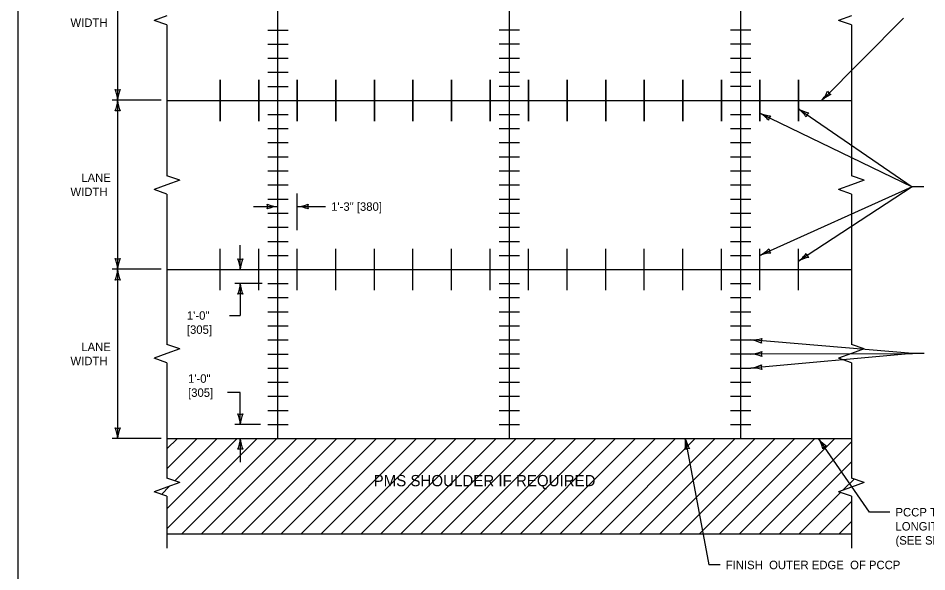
# Model space of a CAD drawing. Extents: x 49979.1 to 50021, y 49966.7 to 50011.4.
# Drawn here: x 49999.38 to 50005.83, y 49992.49 to 49996.41 of the extents above; entities that cross this region are included whole.
import ezdxf

# ---------------------------------------------------------------- set-up
doc = ezdxf.new("R2010")
doc.units = 0
for name, color, linetype in [('Level 1', 7, 'Continuous'), ('Level 2', 7, 'Continuous'), ('Level 3', 7, 'Continuous'), ('Level 4', 7, 'Continuous'), ('Level 6', 7, 'Continuous')]:
    doc.layers.add(name, color=color, linetype=linetype)

msp = doc.modelspace()

# ---------------------------------------------------------------- linework, layer by layer
at = {"layer": 'Level 1'}
for p, q in [((50001.228, 49993.431), (50001.228, 49997.7101)), ((50002.8704, 49993.431), (50002.8704, 49997.7101)), ((50004.5127, 49993.431), (50004.5127, 49997.7101)), ((50000.4398, 49995.8308), (50005.2986, 49995.8308)), ((50000.441, 49994.631), (50005.2998, 49994.631)), ((50000.4398, 49993.431), (50005.2986, 49993.431)), ((50000.4398, 49992.7915), (50001.0793, 49993.431)), ((50000.4398, 49992.9329), (50000.9379, 49993.431)), ((50000.4398, 49993.2157), (50000.6551, 49993.431)), ((50000.4398, 49993.3571), (50000.5136, 49993.431)), ((50000.4962, 49993.1307), (50000.7965, 49993.431)), ((50000.5421, 49992.7524), (50001.2207, 49993.431)), ((50000.6835, 49992.7524), (50001.3622, 49993.431)), ((50000.8249, 49992.7524), (50001.5036, 49993.431)), ((50000.9664, 49992.7524), (50001.645, 49993.431)), ((50001.1078, 49992.7524), (50001.7864, 49993.431)), ((50001.2492, 49992.7524), (50001.9279, 49993.431)), ((50001.3906, 49992.7524), (50002.0693, 49993.431)), ((50001.5321, 49992.7524), (50002.2107, 49993.431)), ((50001.6735, 49992.7524), (50002.3521, 49993.431)), ((50001.8149, 49992.7524), (50002.4935, 49993.431)), ((50001.9563, 49992.7524), (50002.6349, 49993.431)), ((50002.0977, 49992.7524), (50002.7764, 49993.431)), ((50002.2392, 49992.7524), (50002.9178, 49993.431)), ((50002.3806, 49992.7524), (50003.0592, 49993.431)), ((50002.522, 49992.7524), (50003.2007, 49993.431)), ((50002.6634, 49992.7524), (50003.3421, 49993.431)), ((50002.8048, 49992.7524), (50003.4835, 49993.431)), ((50002.9463, 49992.7524), (50003.6249, 49993.431)), ((50003.0877, 49992.7524), (50003.7663, 49993.431)), ((50003.2291, 49992.7524), (50003.9077, 49993.431)), ((50003.3705, 49992.7524), (50004.0492, 49993.431)), ((50003.512, 49992.7524), (50004.1906, 49993.431)), ((50003.6534, 49992.7524), (50004.332, 49993.431)), ((50003.7948, 49992.7524), (50004.4734, 49993.431)), ((50003.9362, 49992.7524), (50004.6149, 49993.431)), ((50004.0776, 49992.7524), (50004.7563, 49993.431)), ((50004.2191, 49992.7524), (50004.8977, 49993.431)), ((50004.3605, 49992.7524), (50005.0391, 49993.431)), ((50004.5019, 49992.7524), (50005.1805, 49993.431)), ((50004.6433, 49992.7524), (50005.2986, 49993.4077)), ((50004.7847, 49992.7524), (50005.2986, 49993.2662)), ((50005.2384, 49993.0646), (50005.3177, 49993.1439)), ((50000.4005, 49993.035), (50000.4578, 49993.0923)), ((50004.9262, 49992.7524), (50005.2221, 49993.0483)), ((50005.0676, 49992.7524), (50005.2986, 49992.9834)), ((50005.209, 49992.7524), (50005.2986, 49992.842)), ((50005.2986, 49992.7524), (50000.4398, 49992.7524))]:
    msp.add_line(p, q, dxfattribs=at)
msp.add_lwpolyline([(49999.3835, 49998.9992), (50016.7501, 49998.9992), (50016.7501, 49987.7988), (49999.3835, 49987.7988)], close=True, dxfattribs=at)
at = {"layer": 'Level 3'}
for p, q in [((50000.0898, 49997.0329), (50000.0898, 49995.8323)), ((50005.6674, 49996.4148), (50005.0876, 49995.8308)), ((50000.3998, 49995.8323), (50000.0498, 49995.8323)), ((50000.0898, 49995.8323), (50000.0898, 49994.6324)), ((50005.8118, 49995.2174), (50005.7276, 49995.2174)), ((50001.365, 49994.9096), (50001.365, 49995.1711)), ((50001.0546, 49995.0775), (50001.228, 49995.0775)), ((50001.365, 49995.0775), (50001.5656, 49995.0775)), ((50000.9605, 49994.6312), (50000.9605, 49994.8046)), ((50000.3998, 49994.6324), (50000.0498, 49994.6324)), ((50000.0898, 49994.6324), (50000.0898, 49993.431)), ((50001.115, 49994.5315), (50000.9205, 49994.5312)), ((50000.9605, 49994.5312), (50000.9605, 49994.3044)), ((50000.8826, 49994.3044), (50000.9605, 49994.3044)), ((50005.816, 49994.0343), (50005.7318, 49994.0343)), ((50000.9605, 49993.7571), (50000.8689, 49993.7571)), ((50000.9605, 49993.5309), (50000.9605, 49993.7571)), ((50001.1038, 49993.5309), (50000.9205, 49993.5309)), ((50000.3998, 49993.431), (50000.0498, 49993.431)), ((50000.9605, 49993.4309), (50000.9605, 49993.2625)), ((50004.1194, 49993.431), (50004.2869, 49992.5341)), ((50005.4272, 49992.9084), (50005.0655, 49993.431)), ((50005.5717, 49992.9084), (50005.4272, 49992.9084)), ((50004.3669, 49992.5341), (50004.2869, 49992.5341))]:
    msp.add_line(p, q, dxfattribs=at)
for points in [[(50004.9233, 49995.7715), (50005.7311, 49995.2174), (50004.9233, 49994.6897)], [(50004.6496, 49995.7402), (50005.7311, 49995.2174), (50004.6496, 49994.7314)], [(50005.7318, 49994.0343), (50005.7318, 49994.0343), (50004.5857, 49994.1313)], [(50004.5857, 49994.0313), (50005.7318, 49994.0343), (50004.5857, 49993.9312)]]:
    msp.add_lwpolyline(points, dxfattribs=at)
for centre, radius, start, end in [((50000.0898, 49995.9605), 0.0548, 252.13882, 287.86118), ((49999.857, 49995.8208), 0.233, 2.82731, 22.07716), ((50000.3119, 49995.8231), 0.2223, 157.45601, 177.63952), ((50004.9144, 49995.9866), 0.233, 318.03472, 337.28457), ((50005.178, 49995.9218), 0.0548, 207.34623, 243.06859), ((49999.8676, 49995.8414), 0.2223, 337.45601, 357.63952), ((50000.3225, 49995.8437), 0.233, 182.82731, 202.07716), ((50005.2388, 49995.6678), 0.2223, 112.66342, 132.84693), ((50004.7901, 49995.5935), 0.2223, 33.00698, 53.19048), ((50005.0455, 49995.9699), 0.233, 238.37828, 257.62813), ((50000.0898, 49995.704), 0.0548, 72.13882, 107.86118), ((50004.5447, 49995.5442), 0.2223, 41.65461, 61.83812), ((50004.7406, 49995.9548), 0.233, 247.02591, 266.27576), ((50004.765, 49995.6844), 0.0548, 136.33742, 172.05978), ((50005.0291, 49995.699), 0.0548, 127.68978, 163.41215), ((50001.2372, 49995.2996), 0.2223, 247.45601, 267.63952), ((50001.0998, 49995.0775), 0.0548, 342.13882, 17.86118), ((50001.2395, 49994.8448), 0.233, 92.82731, 112.07716), ((50001.3535, 49995.3102), 0.233, 272.82731, 292.07716), ((50001.3559, 49994.8554), 0.2223, 67.45601, 87.63952), ((50001.4932, 49995.0775), 0.0548, 162.13882, 197.86118), ((50004.5437, 49994.939), 0.233, 297.02416, 316.27401), ((50004.7323, 49994.5251), 0.2223, 91.65286, 111.83637), ((50004.7666, 49994.784), 0.0548, 186.33567, 222.05803), ((50004.7864, 49994.8783), 0.233, 305.9819, 325.23175), ((50005.0307, 49994.7599), 0.0548, 195.29341, 231.01577), ((50000.0898, 49994.7606), 0.0548, 252.13882, 287.86118), ((49999.857, 49994.6209), 0.233, 2.82731, 22.07716), ((50000.3119, 49994.6233), 0.2223, 157.45601, 177.63952), ((50000.9605, 49994.7594), 0.0548, 252.13882, 287.86118), ((50000.7278, 49994.6197), 0.233, 2.82731, 22.07716), ((50001.1827, 49994.622), 0.2223, 157.45601, 177.63952), ((50005.0371, 49994.4988), 0.2223, 100.6106, 120.79411), ((49999.8676, 49994.6416), 0.2223, 337.45601, 357.63952), ((50000.3225, 49994.6439), 0.233, 182.82731, 202.07716), ((50000.0898, 49994.5042), 0.0548, 72.13882, 107.86118), ((50000.7384, 49994.5403), 0.2223, 337.45601, 357.63952), ((50001.1933, 49994.5427), 0.233, 182.82731, 202.07716), ((50000.9605, 49994.403), 0.0548, 72.13882, 107.86118), ((50004.5939, 49994.3642), 0.233, 267.98771, 287.23756), ((50004.5579, 49993.9107), 0.2223, 62.61641, 82.79992), ((50004.7135, 49994.1205), 0.0548, 157.29922, 193.02158), ((50004.5736, 49994.2639), 0.233, 272.97816, 292.22801), ((50004.5772, 49993.8091), 0.2223, 67.60686, 87.79037), ((50004.714, 49994.0316), 0.0548, 162.28967, 198.01203), ((50004.5535, 49994.1619), 0.233, 277.96632, 297.21617), ((50004.5965, 49993.7091), 0.2223, 72.59502, 92.77853), ((50004.7134, 49993.9427), 0.0548, 167.27783, 203.00019), ((50000.9605, 49993.6591), 0.0548, 252.13882, 287.86118), ((50000.7278, 49993.5194), 0.233, 2.82731, 22.07716), ((50001.1827, 49993.5217), 0.2223, 157.45601, 177.63952), ((50000.0898, 49993.5592), 0.0548, 252.13882, 287.86118), ((49999.857, 49993.4195), 0.233, 2.82731, 22.07716), ((50000.3119, 49993.4218), 0.2223, 157.45601, 177.63952), ((50000.7384, 49993.4402), 0.2223, 337.45601, 357.63952), ((50001.1932, 49993.4425), 0.233, 182.82731, 202.07716), ((50003.8994, 49993.3992), 0.2223, 348.03242, 8.21593), ((50004.3461, 49993.485), 0.233, 193.40372, 212.65357), ((50004.8776, 49993.3121), 0.2223, 12.14239, 32.3259), ((50005.2503, 49993.5729), 0.233, 217.51369, 236.76354), ((50000.9605, 49993.3028), 0.0548, 72.13882, 107.86118), ((50004.1429, 49993.305), 0.0548, 82.71523, 118.43759), ((50005.1385, 49993.3256), 0.0548, 106.8252, 142.54756)]:
    msp.add_arc(centre, radius, start, end, dxfattribs=at)
at = {"layer": 'Level 4'}
for p, q in [((50001.155, 49996.3306), (50001.301, 49996.3306)), ((50002.7974, 49996.3317), (50002.9434, 49996.3317)), ((50004.4398, 49996.3317), (50004.5857, 49996.3317)), ((50001.155, 49996.2305), (50001.301, 49996.2305)), ((50002.7974, 49996.2316), (50002.9434, 49996.2316)), ((50004.4398, 49996.2316), (50004.5857, 49996.2316)), ((50001.155, 49996.1305), (50001.301, 49996.1305)), ((50002.7974, 49996.1316), (50002.9434, 49996.1316)), ((50004.4398, 49996.1316), (50004.5857, 49996.1316)), ((50001.155, 49996.0304), (50001.301, 49996.0304)), ((50002.7974, 49996.0315), (50002.9434, 49996.0315)), ((50004.4398, 49996.0315), (50004.5857, 49996.0315)), ((50000.8176, 49995.6848), (50000.8176, 49995.9768)), ((50000.8176, 49995.9768), (50000.8176, 49995.6848)), ((50001.0913, 49995.6848), (50001.0913, 49995.9768)), ((50001.0913, 49995.9768), (50001.0913, 49995.6848)), ((50001.365, 49995.6848), (50001.365, 49995.9768)), ((50001.365, 49995.9768), (50001.365, 49995.6848)), ((50001.6387, 49995.6848), (50001.6387, 49995.9768)), ((50001.6387, 49995.9768), (50001.6387, 49995.6848)), ((50001.9124, 49995.6848), (50001.9124, 49995.9768)), ((50001.9124, 49995.9768), (50001.9124, 49995.6848)), ((50002.1862, 49995.6848), (50002.1862, 49995.9768)), ((50002.1862, 49995.9768), (50002.1862, 49995.6848)), ((50002.4599, 49995.6848), (50002.4599, 49995.9768)), ((50002.4599, 49995.9768), (50002.4599, 49995.6848)), ((50002.7336, 49995.6848), (50002.7336, 49995.9768)), ((50002.7336, 49995.9768), (50002.7336, 49995.6848)), ((50003.0073, 49995.6848), (50003.0073, 49995.9768)), ((50003.0073, 49995.9768), (50003.0073, 49995.6848)), ((50003.281, 49995.6848), (50003.281, 49995.9768)), ((50003.281, 49995.9768), (50003.281, 49995.6848)), ((50003.5547, 49995.6848), (50003.5547, 49995.9768)), ((50003.5547, 49995.9768), (50003.5547, 49995.6848)), ((50003.8285, 49995.6848), (50003.8285, 49995.9768)), ((50003.8285, 49995.9768), (50003.8285, 49995.6848)), ((50004.1022, 49995.6848), (50004.1022, 49995.9768)), ((50004.1022, 49995.9768), (50004.1022, 49995.6848)), ((50004.3759, 49995.6848), (50004.3759, 49995.9768)), ((50004.3759, 49995.9768), (50004.3759, 49995.6848)), ((50004.6496, 49995.6848), (50004.6496, 49995.9768)), ((50004.6496, 49995.9768), (50004.6496, 49995.6848)), ((50004.9233, 49995.6848), (50004.9233, 49995.9768)), ((50004.9233, 49995.9768), (50004.9233, 49995.6848)), ((50001.155, 49995.9304), (50001.301, 49995.9304)), ((50002.7974, 49995.9314), (50002.9434, 49995.9314)), ((50004.4398, 49995.9314), (50004.5857, 49995.9314)), ((50001.155, 49995.7313), (50001.301, 49995.7313)), ((50002.7974, 49995.7313), (50002.9434, 49995.7313)), ((50004.4398, 49995.7313), (50004.5857, 49995.7313)), ((50001.155, 49995.6313), (50001.301, 49995.6313)), ((50002.7974, 49995.6313), (50002.9434, 49995.6313)), ((50004.4398, 49995.6313), (50004.5857, 49995.6313)), ((50001.155, 49995.5312), (50001.301, 49995.5312)), ((50002.7974, 49995.5312), (50002.9434, 49995.5312)), ((50004.4398, 49995.5312), (50004.5857, 49995.5312)), ((50001.155, 49995.4312), (50001.301, 49995.4312)), ((50002.7974, 49995.4312), (50002.9434, 49995.4312)), ((50004.4398, 49995.4312), (50004.5857, 49995.4312)), ((50001.155, 49995.3311), (50001.301, 49995.3311)), ((50002.7974, 49995.3311), (50002.9434, 49995.3311)), ((50004.4398, 49995.3311), (50004.5857, 49995.3311)), ((50001.155, 49995.2311), (50001.301, 49995.2311)), ((50002.7974, 49995.2311), (50002.9434, 49995.2311)), ((50004.4398, 49995.2311), (50004.5857, 49995.2311)), ((50001.155, 49995.131), (50001.301, 49995.131)), ((50002.7974, 49995.131), (50002.9434, 49995.131)), ((50004.4398, 49995.131), (50004.5857, 49995.131)), ((50001.155, 49995.031), (50001.301, 49995.031)), ((50002.7974, 49995.031), (50002.9434, 49995.031)), ((50004.4398, 49995.031), (50004.5857, 49995.031)), ((50001.155, 49994.9309), (50001.301, 49994.9309)), ((50002.7974, 49994.9309), (50002.9434, 49994.9309)), ((50004.4398, 49994.9309), (50004.5857, 49994.9309)), ((50001.155, 49994.8309), (50001.301, 49994.8309)), ((50002.7974, 49994.8309), (50002.9434, 49994.8309)), ((50004.4398, 49994.8309), (50004.5857, 49994.8309)), ((50000.8176, 49994.485), (50000.8176, 49994.777)), ((50001.0913, 49994.485), (50001.0913, 49994.777)), ((50001.365, 49994.485), (50001.365, 49994.777)), ((50001.6387, 49994.485), (50001.6387, 49994.777)), ((50001.9124, 49994.485), (50001.9124, 49994.777)), ((50002.1862, 49994.485), (50002.1862, 49994.777)), ((50002.4599, 49994.485), (50002.4599, 49994.777)), ((50002.7336, 49994.485), (50002.7336, 49994.777)), ((50003.0073, 49994.485), (50003.0073, 49994.777)), ((50003.281, 49994.485), (50003.281, 49994.777)), ((50003.5547, 49994.485), (50003.5547, 49994.777)), ((50003.8285, 49994.485), (50003.8285, 49994.777)), ((50004.1022, 49994.485), (50004.1022, 49994.777)), ((50004.3759, 49994.485), (50004.3759, 49994.777)), ((50004.6496, 49994.485), (50004.6496, 49994.777)), ((50004.9233, 49994.485), (50004.9233, 49994.777)), ((50001.155, 49994.7308), (50001.301, 49994.7308)), ((50002.7974, 49994.7308), (50002.9434, 49994.7308)), ((50004.4398, 49994.7308), (50004.5857, 49994.7308)), ((50001.155, 49994.5315), (50001.301, 49994.5315)), ((50002.7974, 49994.5315), (50002.9434, 49994.5315)), ((50004.4398, 49994.5315), (50004.5857, 49994.5315)), ((50001.155, 49994.4315), (50001.301, 49994.4315)), ((50002.7974, 49994.4315), (50002.9434, 49994.4315)), ((50004.4398, 49994.4315), (50004.5857, 49994.4315)), ((50001.155, 49994.3314), (50001.301, 49994.3314)), ((50002.7974, 49994.3314), (50002.9434, 49994.3314)), ((50004.4398, 49994.3314), (50004.5857, 49994.3314)), ((50001.155, 49994.2313), (50001.301, 49994.2313)), ((50002.7974, 49994.2314), (50002.9434, 49994.2314)), ((50004.4398, 49994.2314), (50004.5857, 49994.2314)), ((50001.155, 49994.1313), (50001.301, 49994.1313)), ((50002.7974, 49994.1313), (50002.9434, 49994.1313)), ((50004.4398, 49994.1313), (50004.5857, 49994.1313)), ((50001.155, 49994.0312), (50001.301, 49994.0312)), ((50002.7974, 49994.0313), (50002.9434, 49994.0313)), ((50004.4398, 49994.0313), (50004.5857, 49994.0313)), ((50001.155, 49993.9312), (50001.301, 49993.9312)), ((50002.7974, 49993.9312), (50002.9434, 49993.9312)), ((50004.4398, 49993.9312), (50004.5857, 49993.9312)), ((50001.155, 49993.8311), (50001.301, 49993.8311)), ((50002.7974, 49993.8311), (50002.9434, 49993.8311)), ((50004.4398, 49993.8311), (50004.5857, 49993.8311)), ((50001.155, 49993.7311), (50001.301, 49993.7311)), ((50002.7974, 49993.7311), (50002.9434, 49993.7311)), ((50004.4398, 49993.7311), (50004.5857, 49993.7311)), ((50001.155, 49993.631), (50001.301, 49993.631)), ((50002.7974, 49993.631), (50002.9434, 49993.631)), ((50004.4398, 49993.631), (50004.5857, 49993.631)), ((50001.155, 49993.531), (50001.301, 49993.531)), ((50002.7974, 49993.531), (50002.9434, 49993.531)), ((50004.4398, 49993.531), (50004.5857, 49993.531))]:
    msp.add_line(p, q, dxfattribs=at)
at = {"layer": 'Level 6'}
for p, q in [((50000.4398, 49996.4316), (50000.3484, 49996.3992)), ((50005.2986, 49996.4316), (50005.2072, 49996.3992)), ((50000.4398, 49996.3668), (50000.3484, 49996.3992)), ((50000.4398, 49996.3668), (50000.4398, 49995.2964)), ((50005.2986, 49996.3668), (50005.2072, 49996.3992)), ((50005.2986, 49996.3668), (50005.2987, 49995.2964)), ((50000.5312, 49995.264), (50000.4398, 49995.2964)), ((50000.5312, 49995.264), (50000.4398, 49995.2316)), ((50005.39, 49995.264), (50005.2986, 49995.2964)), ((50005.39, 49995.264), (50005.2986, 49995.2316)), ((50000.4398, 49995.2316), (50000.3484, 49995.1992)), ((50000.4398, 49995.1668), (50000.3484, 49995.1992)), ((50005.2986, 49995.2316), (50005.2072, 49995.1992)), ((50005.2986, 49995.1668), (50005.2072, 49995.1992)), ((50000.4398, 49995.1668), (50000.4398, 49994.0992)), ((50005.2986, 49995.1668), (50005.2987, 49994.0992)), ((50000.5312, 49994.0668), (50000.4398, 49994.0992)), ((50005.39, 49994.0668), (50005.2986, 49994.0992)), ((50000.4398, 49994.0344), (50000.3484, 49994.002)), ((50000.5312, 49994.0668), (50000.4398, 49994.0344)), ((50005.2986, 49994.0344), (50005.2072, 49994.002)), ((50005.39, 49994.0668), (50005.2986, 49994.0344)), ((50000.4398, 49993.9696), (50000.3484, 49994.002)), ((50000.4398, 49993.9696), (50000.4398, 49993.1507)), ((50005.2986, 49993.9696), (50005.2072, 49994.002)), ((50005.2986, 49993.9696), (50005.2986, 49993.5186)), ((50005.2986, 49993.6017), (50005.2986, 49993.1507)), ((50000.5312, 49993.1183), (50000.4398, 49993.1507)), ((50005.39, 49993.1183), (50005.2986, 49993.1507)), ((50000.4398, 49993.0859), (50000.3484, 49993.0535)), ((50000.5312, 49993.1183), (50000.4398, 49993.0859)), ((50005.2986, 49993.0859), (50005.2072, 49993.0535)), ((50005.39, 49993.1183), (50005.2986, 49993.0859)), ((50000.4398, 49993.0211), (50000.3484, 49993.0535)), ((50000.4398, 49993.0211), (50000.4398, 49992.6524)), ((50005.2986, 49993.0211), (50005.2072, 49993.0535)), ((50005.2986, 49993.0211), (50005.2986, 49992.6524))]:
    msp.add_line(p, q, dxfattribs=at)

# ---------------------------------------------------------------- texts
at = {"layer": 'Level 2'}
for s, height, p in [('WIDTH', 0.06, (49999.7548, 49996.3526)), ('LANE', 0.06, (49999.8318, 49995.2523)), ('WIDTH', 0.06, (49999.7548, 49995.1523)), ('1\'-3" [380]', 0.06, (50001.6056, 49995.0475)), ('1\'-0"', 0.06, (50000.5813, 49994.2744)), ('[305]', 0.06, (50000.5813, 49994.1744)), ('LANE', 0.06, (49999.8318, 49994.0517)), ('WIDTH', 0.06, (49999.7548, 49993.9517)), ('1\'-0"', 0.06, (50000.5894, 49993.8271)), ('[305]', 0.06, (50000.5894, 49993.7271)), ('PMS SHOULDER IF REQUIRED', 0.08, (50001.9068, 49993.0926)), ('PCCP TO PMS', 0.06, (50005.6117, 49992.8784)), ('LONGITUDINAL JOINT', 0.06, (50005.6117, 49992.7784)), ('(SEE SECTION VIEW)', 0.06, (50005.6117, 49992.6784)), ('FINISH  OUTER EDGE  OF PCCP', 0.06, (50004.4069, 49992.5041))]:
    msp.add_text(s, height=height, dxfattribs=at).set_placement(p)

doc.saveas('drawing.dxf')
